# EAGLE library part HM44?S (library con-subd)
SUB-D
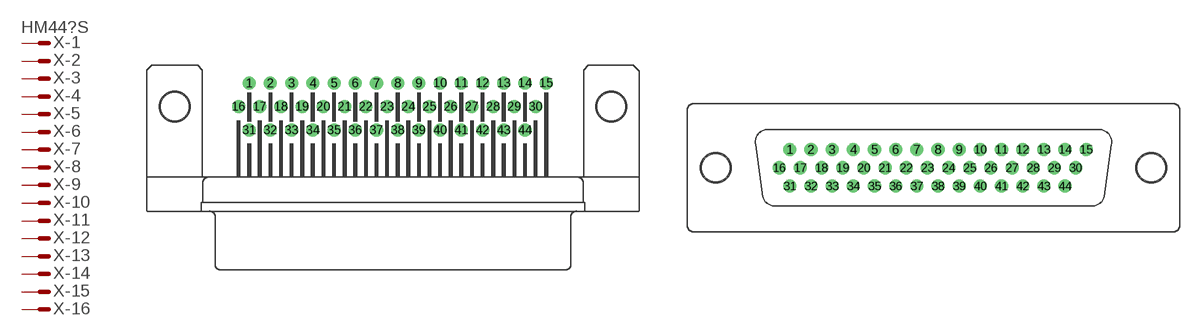
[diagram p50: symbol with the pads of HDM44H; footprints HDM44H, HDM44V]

Designator prefix X; gates -1=MV -2=M -3=M -4=M -5=M -6=M -7=M -8=M -9=M -10=M -11=M -12=M -13=M -14=M -15=M -16=M -17=M -18=M -19=M -20=M -21=M -22=M -23=M -24=M -25=M -26=M -27=M -28=M -29=M -30=M -31=M -32=M -33=M -34=M -35=M -36=M -37=M -38=M -39=M -40=M -41=M -42=M -43=M -44=M

## HM44HS (OC_FARNELL: unknown; OC_NEWARK: unknown)  [HDM44H]
1  -1:M  pas
2  -2:M  pas
3  -3:M  pas
4  -4:M  pas
5  -5:M  pas
6  -6:M  pas
7  -7:M  pas
8  -8:M  pas
9  -9:M  pas
10  -10:M  pas
11  -11:M  pas
12  -12:M  pas
13  -13:M  pas
14  -14:M  pas
15  -15:M  pas
16  -16:M  pas
17  -17:M  pas
18  -18:M  pas
19  -19:M  pas
20  -20:M  pas
21  -21:M  pas
22  -22:M  pas
23  -23:M  pas
24  -24:M  pas
25  -25:M  pas
26  -26:M  pas
27  -27:M  pas
28  -28:M  pas
29  -29:M  pas
30  -30:M  pas
31  -31:M  pas
32  -32:M  pas
33  -33:M  pas
34  -34:M  pas
35  -35:M  pas
36  -36:M  pas
37  -37:M  pas
38  -38:M  pas
39  -39:M  pas
40  -40:M  pas
41  -41:M  pas
42  -42:M  pas
43  -43:M  pas
44  -44:M  pas

## HM44VS (OC_FARNELL: unknown; OC_NEWARK: unknown)  [HDM44V]
Pads as for HDM44H

## Footprint HDM44H (pad centres in mm)
SUB-D
drill 0.9 round: 1 -15.497,2.54; 2 -13.211,2.54; 3 -10.925,2.54; 4 -8.639,2.54; 5 -6.353,2.54; 6 -4.067,2.54; 7 -1.781,2.54; 8 0.505,2.54; 9 2.791,2.54; 10 5.077,2.54; 11 7.363,2.54; 12 9.649,2.54; 13 11.935,2.54; 14 14.221,2.54; 15 16.507,2.54; 16 -16.64,0; 17 -14.354,0; 18 -12.068,0; 19 -9.782,0; 20 -7.496,0; 21 -5.21,0; 22 -2.924,0; 23 -0.638,0; 24 1.648,0; 25 3.934,0; 26 6.22,0; 27 8.506,0; 28 10.792,0; 29 13.078,0; 30 15.364,0; 31 -15.497,-2.54; 32 -13.211,-2.54; 33 -10.925,-2.54; 34 -8.639,-2.54; 35 -6.353,-2.54; 36 -4.067,-2.54; 37 -1.781,-2.54; 38 0.505,-2.54; 39 2.791,-2.54; 40 5.077,-2.54; 41 7.363,-2.54; 42 9.649,-2.54; 43 11.935,-2.54; 44 14.221,-2.54
hole 3 at -23.52,0
hole 3 at 23.52,0

## Footprint HDM44V (pad centres in mm)
SUB-D
drill 0.9 round: 1 -15.516,1.98; 2 -13.23,1.98; 3 -10.944,1.98; 4 -8.658,1.98; 5 -6.372,1.98; 6 -4.086,1.98; 7 -1.8,1.98; 8 0.486,1.98; 9 2.772,1.98; 10 5.058,1.98; 11 7.344,1.98; 12 9.63,1.98; 13 11.916,1.98; 14 14.202,1.98; 15 16.488,1.98; 16 -16.659,0; 17 -14.373,0; 18 -12.087,0; 19 -9.801,0; 20 -7.515,0; 21 -5.229,0; 22 -2.943,0; 23 -0.657,0; 24 1.629,0; 25 3.915,0; 26 6.201,0; 27 8.487,0; 28 10.773,0; 29 13.059,0; 30 15.345,0; 31 -15.516,-1.98; 32 -13.23,-1.98; 33 -10.944,-1.98; 34 -8.658,-1.98; 35 -6.372,-1.98; 36 -4.086,-1.98; 37 -1.8,-1.98; 38 0.486,-1.98; 39 2.772,-1.98; 40 5.058,-1.98; 41 7.344,-1.98; 42 9.63,-1.98; 43 11.916,-1.98; 44 14.202,-1.98
hole 3 at -23.52,0
hole 3 at 23.52,0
